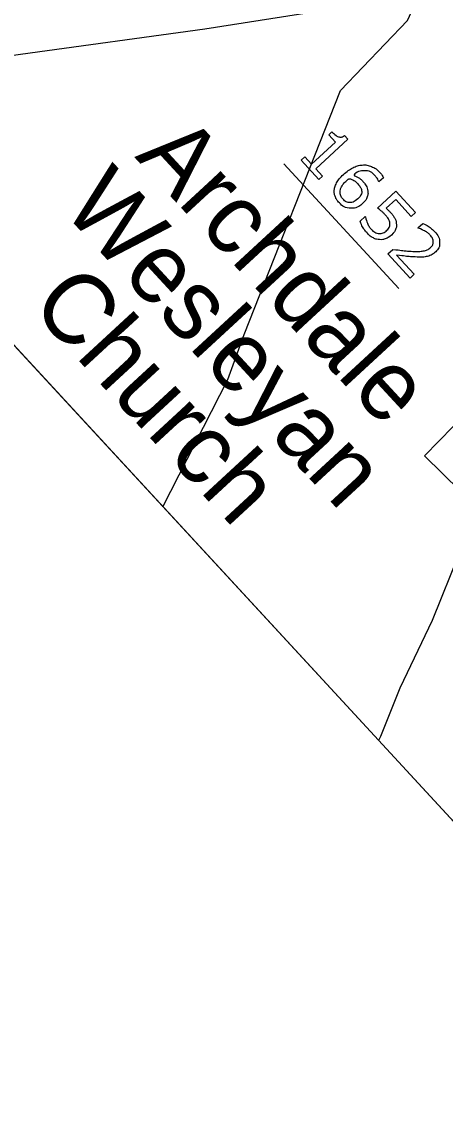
# Model space of a CAD drawing. Extents: x 1695041 to 1706254, y 786537 to 798223.
# Drawn here: x 1703133.2 to 1703183.7, y 796409.4 to 796540 of the extents above; entities that cross this region are included whole.
import ezdxf

# ---------------------------------------------------------------- set-up
doc = ezdxf.new("R2010")
doc.units = 0
for name, color, linetype in [('Default', 7, 'Continuous'), ('Old_Level_29', 7, 'Continuous'), ('Old_Level_30', 7, 'Continuous'), ('Old_Level_32', 7, 'Continuous')]:
    doc.layers.add(name, color=color, linetype=linetype)

msp = doc.modelspace()

# ---------------------------------------------------------------- linework, layer by layer
at = {"layer": 'Default'}
for p, q in [((1702636.99, 797037.98), (1703265.12, 796357.5)), ((1703164.48, 796523.03), (1703178.21, 796508.16))]:
    msp.add_line(p, q, dxfattribs=at)
for points in [[(1703207.65, 797564.73), (1702636.99, 797037.98), (1703265.12, 796357.5), (1703835.77, 796884.26)], [(1703168.69, 796521.19), (1703166.57, 796523.49), (1703167.01, 796523.89), (1703167.82, 796523), (1703170.67, 796525.63), (1703169.85, 796526.51), (1703170.24, 796526.87)], [(1703171.74, 796526.43), (1703172.15, 796525.99), (1703168.33, 796522.46), (1703169.13, 796521.59), (1703168.69, 796521.19)], [(1703176.4, 796521.38), (1703175.85, 796520.88), (1703175.83, 796520.91)], [(1703175.66, 796517.77), (1703177.85, 796519.79), (1703180.2, 796517.24), (1703179.7, 796516.78), (1703177.85, 796518.78), (1703176.72, 796517.74)], [(1703173.59, 796516.2), (1703174.19, 796516.76), (1703174.23, 796516.72)], [(1703180.51, 796515.36), (1703180.48, 796515.39), (1703181.08, 796515.94)], [(1703179.57, 796509.41), (1703176.91, 796512.29), (1703177.51, 796512.84)], [(1703177.95, 796512.15), (1703180.06, 796509.87), (1703179.57, 796509.41)]]:
    msp.add_lwpolyline(points, dxfattribs=at)
msp.add_lwpolyline([(1703184.72, 796491.72), (1703186.59, 796489.88), (1703189.06, 796492.39), (1703188.01, 796493.42), (1703188.52, 796493.95), (1703189.58, 796492.91), (1703191.53, 796494.89), (1703192.05, 796494.38), (1703190.11, 796492.39), (1703191.16, 796491.36), (1703190.64, 796490.83), (1703189.59, 796491.87), (1703187.12, 796489.36), (1703189.02, 796487.49), (1703185.57, 796483.98), (1703181.27, 796488.21)], close=True, dxfattribs=at)
for points in [[(1703170.24, 796526.87), (1703170.4, 796526.69), (1703170.62, 796526.51), (1703170.84, 796526.34), (1703171, 796526.28), (1703171.19, 796526.22), (1703171.37, 796526.24), (1703171.55, 796526.27), (1703171.74, 796526.43)], [(1703173.9, 796518.31), (1703173.25, 796517.71), (1703172.45, 796517.76), (1703171.65, 796517.81), (1703171.08, 796518.43), (1703170.79, 796518.74), (1703170.65, 796519.09), (1703170.51, 796519.43), (1703170.52, 796519.81), (1703170.53, 796520.27), (1703170.8, 796520.76), (1703171.06, 796521.26), (1703171.61, 796521.76), (1703172.18, 796522.28), (1703172.73, 796522.57), (1703173.28, 796522.85), (1703173.86, 796522.9), (1703174.41, 796522.94), (1703174.96, 796522.71), (1703175.51, 796522.48), (1703175.99, 796521.96), (1703176.15, 796521.79), (1703176.24, 796521.66), (1703176.33, 796521.53), (1703176.4, 796521.38)], [(1703175.83, 796520.91), (1703175.8, 796521.03), (1703175.69, 796521.22), (1703175.58, 796521.42), (1703175.42, 796521.59), (1703174.86, 796522.2), (1703174.14, 796522.21), (1703173.42, 796522.22), (1703172.71, 796521.68), (1703173.08, 796521.57), (1703173.37, 796521.41), (1703173.66, 796521.25), (1703173.94, 796520.94), (1703174.19, 796520.67), (1703174.33, 796520.42), (1703174.47, 796520.17), (1703174.52, 796519.81), (1703174.57, 796519.4), (1703174.43, 796519.03), (1703174.28, 796518.66), (1703173.9, 796518.31)], [(1703173.34, 796518.87), (1703173.6, 796519.11), (1703173.71, 796519.35), (1703173.81, 796519.59), (1703173.77, 796519.88), (1703173.74, 796520.1), (1703173.62, 796520.28), (1703173.5, 796520.47), (1703173.34, 796520.64), (1703173.12, 796520.89), (1703172.87, 796521.04), (1703172.62, 796521.2), (1703172.3, 796521.3), (1703172.23, 796521.25), (1703172.17, 796521.2), (1703172.11, 796521.15), (1703172.02, 796521.07), (1703171.57, 796520.65), (1703171.4, 796520.32), (1703171.22, 796519.99), (1703171.22, 796519.69), (1703171.22, 796519.44), (1703171.3, 796519.23), (1703171.38, 796519.03), (1703171.55, 796518.85), (1703171.93, 796518.44), (1703172.4, 796518.43), (1703172.87, 796518.43), (1703173.34, 796518.87)], [(1703174.23, 796516.72), (1703174.3, 796516.35), (1703174.48, 796515.94), (1703174.67, 796515.53), (1703174.94, 796515.22), (1703175.13, 796515.02), (1703175.36, 796514.89), (1703175.6, 796514.75), (1703175.88, 796514.73), (1703176.11, 796514.72), (1703176.34, 796514.81), (1703176.58, 796514.91), (1703176.8, 796515.12), (1703177.02, 796515.32), (1703177.1, 796515.54), (1703177.18, 796515.75), (1703177.15, 796515.97), (1703177.12, 796516.22), (1703176.97, 796516.47), (1703176.82, 796516.72), (1703176.58, 796516.98), (1703176.35, 796517.24), (1703176.1, 796517.44), (1703175.85, 796517.64), (1703175.66, 796517.77)], [(1703176.72, 796517.74), (1703176.85, 796517.63), (1703176.97, 796517.51), (1703177.1, 796517.38), (1703177.18, 796517.29), (1703177.5, 796516.94), (1703177.68, 796516.63), (1703177.87, 796516.32), (1703177.92, 796515.96), (1703177.97, 796515.59), (1703177.84, 796515.24), (1703177.71, 796514.88), (1703177.33, 796514.54)], [(1703177.33, 796514.54), (1703177.04, 796514.26), (1703176.66, 796514.12), (1703176.29, 796513.98), (1703175.93, 796514), (1703175.55, 796514.02), (1703175.18, 796514.2), (1703174.81, 796514.39), (1703174.46, 796514.76), (1703174.14, 796515.11), (1703173.92, 796515.5), (1703173.69, 796515.88), (1703173.59, 796516.2)], [(1703177.51, 796512.84), (1703178.05, 796512.78), (1703178.58, 796512.71), (1703179.12, 796512.65), (1703179.61, 796512.62), (1703180.64, 796512.56), (1703181.14, 796512.65), (1703181.64, 796512.73), (1703182, 796513.07), (1703182.33, 796513.37), (1703182.32, 796513.76), (1703182.3, 796514.15), (1703181.94, 796514.55), (1703181.7, 796514.81), (1703181.33, 796515.02), (1703180.96, 796515.24), (1703180.51, 796515.36)], [(1703181.08, 796515.94), (1703181.36, 796515.83), (1703181.76, 796515.57), (1703182.15, 796515.3), (1703182.45, 796514.99), (1703183.05, 796514.33), (1703183.08, 796513.67), (1703183.1, 796513.01), (1703182.57, 796512.51), (1703182.32, 796512.29), (1703182.06, 796512.16), (1703181.79, 796512.03), (1703181.49, 796511.97), (1703181.21, 796511.92), (1703180.91, 796511.91), (1703180.6, 796511.91), (1703180.19, 796511.93), (1703179.61, 796511.96), (1703179.03, 796512.02), (1703178.45, 796512.09), (1703177.95, 796512.15)]]:
    msp.add_open_spline(points, degree=3, dxfattribs=at)
at = {"layer": 'Old_Level_29'}
msp.add_lwpolyline([(1703104.13, 796531.91), (1703117.88, 796533.95), (1703133.1, 796536.12), (1703155.07, 796539.16), (1703169.57, 796541.41), (1703176.3, 796542.48), (1703187.74, 796544.39), (1703190.8, 796544.62), (1703195.34, 796544.81), (1703199.04, 796544.37), (1703202.96, 796543.84), (1703206.7, 796542.73), (1703210.79, 796541.08), (1703216.47, 796537.44)], dxfattribs=at)
at = {"layer": 'Old_Level_30'}
msp.add_lwpolyline([(1703150.08, 796482.13), (1703157.83, 796497.33), (1703159.76, 796502.7), (1703171.26, 796531.8), (1703179.26, 796540.13), (1703184.49, 796551.62), (1703184.43, 796554.65), (1703186.95, 796557.98), (1703193.82, 796575.14), (1703213.3, 796600.03), (1703220.8, 796607.33), (1703230.96, 796621.24), (1703232.05, 796624.82), (1703234.9, 796628.46), (1703239.05, 796638.05)], dxfattribs=at)
at = {"layer": 'Old_Level_32'}
msp.add_lwpolyline([(1703216.47, 796537.44), (1703207.81, 796522.16), (1703203.94, 796515.64), (1703200.93, 796510.73), (1703194.45, 796498.57), (1703193.51, 796496.42), (1703188.81, 796484.94), (1703182.2, 796468.56), (1703178.32, 796460.5), (1703176.02, 796454.73), (1703175.81, 796454.26)], dxfattribs=at)

# ---------------------------------------------------------------- texts
at = {"layer": 'Default'}
for s, p in [('Archdale', (1703146.63, 796523.87)), ('Wesleyan', (1703137.85, 796517.65)), ('Church', (1703134.06, 796506.01))]:
    msp.add_text(s, height=8.385, rotation=312.7091, dxfattribs=at).set_placement(p)

doc.saveas('drawing.dxf')
